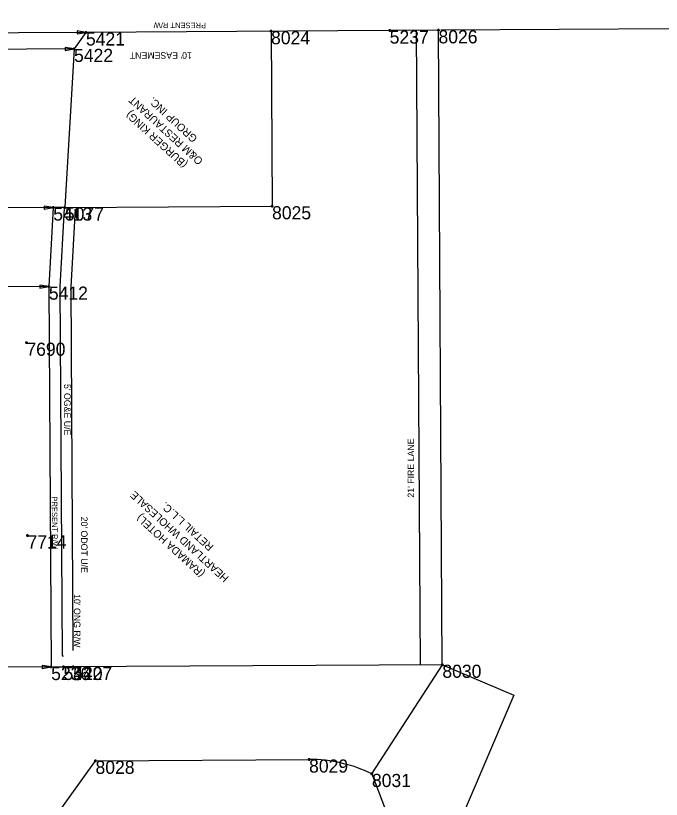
# Model space of a CAD drawing. Extents: x 2145146 to 2158053, y 137507 to 150829.
# Drawn here: x 2150930 to 2151520, y 144848 to 145565 of the extents above; entities that cross this region are included whole.
import ezdxf

# ---------------------------------------------------------------- set-up
doc = ezdxf.new("R2010")
doc.units = 0
for name, color, linetype in [('ALIGN_Cogo Points', 7, 'Continuous'), ('ALIGN_ROW Dimension', 7, 'Continuous'), ('ALIGN_ROW Line', 7, 'Continuous'), ('ALIGN_ROW Text', 7, 'Continuous'), ('PLSS_Easement', 7, 'Continuous'), ('PLSS_Property Line', 7, 'Continuous'), ('PLSS_Text', 7, 'Continuous'), ('PLSS_Text_TURNED OFF', 7, 'Continuous')]:
    doc.layers.add(name, color=color, linetype=linetype)

# ---------------------------------------------------------------- blocks, each defined once
blk = doc.blocks.new('Arrowhd')
at = {"layer": 'PLSS_Property Line'}
blk.add_lwpolyline([(0.125, -0.021), (0.125, 0.021), (0, 0)], close=True, dxfattribs=at)

msp = doc.modelspace()

# ---------------------------------------------------------------- linework, layer by layer
at = {"layer": 'ALIGN_Cogo Points'}
for points in [[(2150994.46, 145549.36), (2150994.46, 145550.56), (2150994.46, 145549.36), (2150993.26, 145549.36), (2150994.46, 145549.36), (2150994.46, 145548.16), (2150994.46, 145549.36), (2150995.66, 145549.36)], [(2151163.64, 145550.46), (2151163.64, 145551.66), (2151163.64, 145550.46), (2151162.44, 145550.46), (2151163.64, 145550.46), (2151163.64, 145549.26), (2151163.64, 145550.46), (2151164.84, 145550.46)], [(2151272.08, 145551.07), (2151272.08, 145552.27), (2151272.08, 145551.07), (2151270.88, 145551.07), (2151272.08, 145551.07), (2151272.08, 145549.87), (2151272.08, 145551.07), (2151273.28, 145551.07)], [(2151316.66, 145551.32), (2151316.66, 145552.52), (2151316.66, 145551.32), (2151315.46, 145551.32), (2151316.66, 145551.32), (2151316.66, 145550.12), (2151316.66, 145551.32), (2151317.86, 145551.32)], [(2150983.58, 145534.3), (2150983.58, 145535.5), (2150983.58, 145534.3), (2150982.38, 145534.3), (2150983.58, 145534.3), (2150983.58, 145533.1), (2150983.58, 145534.3), (2150984.78, 145534.3)], [(2150964.56, 145389.31), (2150964.56, 145390.51), (2150964.56, 145389.31), (2150963.36, 145389.31), (2150964.56, 145389.31), (2150964.56, 145388.11), (2150964.56, 145389.31), (2150965.76, 145389.31)], [(2150975.26, 145389.37), (2150975.26, 145390.57), (2150975.26, 145389.37), (2150974.06, 145389.37), (2150975.26, 145389.37), (2150975.26, 145388.17), (2150975.26, 145389.37), (2150976.46, 145389.37)], [(2151164.56, 145390.47), (2151164.56, 145391.67), (2151164.56, 145390.47), (2151163.36, 145390.47), (2151164.56, 145390.47), (2151164.56, 145389.27), (2151164.56, 145390.47), (2151165.76, 145390.47)], [(2150960.58, 145317), (2150960.58, 145318.2), (2150960.58, 145317), (2150959.38, 145317), (2150960.58, 145317), (2150960.58, 145315.8), (2150960.58, 145317), (2150961.78, 145317)], [(2150940.05, 145265.73), (2150940.05, 145266.93), (2150940.05, 145265.73), (2150938.85, 145265.73), (2150940.05, 145265.73), (2150940.05, 145264.53), (2150940.05, 145265.73), (2150941.25, 145265.73)], [(2150941.1, 145089.57), (2150941.1, 145090.77), (2150941.1, 145089.57), (2150939.9, 145089.57), (2150941.1, 145089.57), (2150941.1, 145088.37), (2150941.1, 145089.57), (2150942.3, 145089.57)], [(2151320.21, 144971.36), (2151320.21, 144972.56), (2151320.21, 144971.36), (2151319.01, 144971.36), (2151320.21, 144971.36), (2151320.21, 144970.16), (2151320.21, 144971.36), (2151321.41, 144971.36)], [(2150962.67, 144969.29), (2150962.67, 144970.49), (2150962.67, 144969.29), (2150961.47, 144969.29), (2150962.67, 144969.29), (2150962.67, 144968.09), (2150962.67, 144969.29), (2150963.87, 144969.29)], [(2150973.99, 144969.36), (2150973.99, 144970.56), (2150973.99, 144969.36), (2150972.79, 144969.36), (2150973.99, 144969.36), (2150973.99, 144968.16), (2150973.99, 144969.36), (2150975.19, 144969.36)], [(2150982.69, 144969.28), (2150982.69, 144970.48), (2150982.69, 144969.28), (2150981.49, 144969.28), (2150982.69, 144969.28), (2150982.69, 144968.08), (2150982.69, 144969.28), (2150983.89, 144969.28)], [(2151003.22, 144883.54), (2151003.22, 144884.74), (2151003.22, 144883.54), (2151002.02, 144883.54), (2151003.22, 144883.54), (2151003.22, 144882.34), (2151003.22, 144883.54), (2151004.42, 144883.54)], [(2151198.4, 144884.72), (2151198.4, 144885.92), (2151198.4, 144884.72), (2151197.2, 144884.72), (2151198.4, 144884.72), (2151198.4, 144883.52), (2151198.4, 144884.72), (2151199.6, 144884.72)], [(2151255.84, 144871.52), (2151255.84, 144872.72), (2151255.84, 144871.52), (2151254.64, 144871.52), (2151255.84, 144871.52), (2151255.84, 144870.32), (2151255.84, 144871.52), (2151257.04, 144871.52)]]:
    msp.add_lwpolyline(points, dxfattribs=at)
at = {"layer": 'ALIGN_ROW Dimension'}
for points in [[(2150994.46, 145549.36), (2150809.35, 145548.25)], [(2150983.58, 145534.3), (2150809.44, 145533.25)], [(2150964.56, 145389.31), (2150810.31, 145388.39)], [(2150960.58, 145317), (2150810.74, 145316.1)], [(2150962.66, 144969.3), (2150812.83, 144968.4)]]:
    msp.add_lwpolyline(points, dxfattribs=at)
at = {"layer": 'ALIGN_ROW Line'}
for points in [[(2151901.3, 145564.63), (2151901.3, 145564.63), (2151751.23, 145563.78), (2151751.29, 145553.78), (2151318.93, 145551.33)], [(2151316.66, 145551.32), (2150994.46, 145549.36), (2150983.58, 145534.3), (2150975.27, 145389.44)], [(2150964.56, 145389.31), (2150960.58, 145317), (2150962.67, 144969.29), (2150973.99, 144969.36)], [(2150975.26, 145389.37), (2150964.56, 145389.31)]]:
    msp.add_lwpolyline(points, dxfattribs=at)
at = {"layer": 'PLSS_Easement'}
for points in [[(2151300.13, 144971.21), (2151296.65, 145551.17)], [(2150974.55, 145388.76), (2150970.58, 145316.75), (2150972.6, 144979.35), (2150973.93, 144979.36)], [(2150984.53, 145388.21), (2150980.58, 145316.51), (2150982.57, 144984.38)]]:
    msp.add_lwpolyline(points, dxfattribs=at)
at = {"layer": 'PLSS_Property Line'}
for p, q in [((2151255.84, 144871.52), (2151320.21, 144971.36)), ((2151320.21, 144971.36), (2151385.43, 144943.51)), ((2151385.43, 144943.51), (2151327.59, 144807.73))]:
    msp.add_line(p, q, dxfattribs=at)
for points in [[(2151163.62, 145550.39), (2151164.56, 145390.47)], [(2151163.64, 145550.46), (2151164.56, 145390.47)], [(2151320.13, 144971.33), (2151316.65, 145551.29)], [(2150975.26, 145389.37), (2151164.56, 145390.47)], [(2151320.13, 144971.36), (2150973.99, 144969.36)], [(2150966.92, 144832.96), (2151003.22, 144883.54), (2151198.4, 144884.72), (2151198.4, 144884.72)], [(2151255.84, 144871.52), (2151255.84, 144871.52), (2151270.67, 144832.3)]]:
    msp.add_lwpolyline(points, dxfattribs=at)
msp.add_arc((2151199.18, 144756.57), 128.15, 63.7592, 90.34776, dxfattribs=at)

# ---------------------------------------------------------------- block references
at = {"layer": 'ALIGN_ROW Dimension', "xscale": 65.00000000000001, "yscale": 64.99999999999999, "rotation": -179.65177652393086}
for p in [(2150994.46, 145549.36), (2150983.58, 145534.3), (2150964.56, 145389.31), (2150960.58, 145317), (2150962.66, 144969.3)]:
    msp.add_blockref('Arrowhd', p, dxfattribs=at)

# ---------------------------------------------------------------- texts
at = {"layer": 'ALIGN_Cogo Points'}
for s, p in [('5421', (2150994.46, 145537.36)), ('8024', (2151163.64, 145538.46)), ('5237', (2151272.08, 145539.07)), ('8026', (2151316.66, 145539.32)), ('5422', (2150983.58, 145522.3)), ('5413', (2150964.56, 145377.31)), ('5077', (2150975.26, 145377.37)), ('8025', (2151164.56, 145378.47)), ('5412', (2150960.58, 145305)), ('7690', (2150940.05, 145253.73)), ('7714', (2150941.1, 145077.57)), ('5236', (2150962.67, 144957.29)), ('5420', (2150973.99, 144957.36)), ('5427', (2150982.69, 144957.28)), ('8030', (2151320.21, 144959.36)), ('8028', (2151003.22, 144871.54)), ('8029', (2151198.4, 144872.72)), ('8031', (2151255.84, 144859.52))]:
    msp.add_text(s, height=12, dxfattribs=at).set_placement(p)
at = {"layer": 'ALIGN_ROW Text'}
for rotation, p in [(179.73131, (2151104.31, 145558.18)), (270.6018, (2150963.19, 145125.17))]:
    msp.add_text('PRESENT R/W', height=5, rotation=rotation, dxfattribs=at).set_placement(p)
at = {"layer": 'PLSS_Text'}
for s, rotation, p in [("10' EASEMENT", 180, (2151091.29, 145531.24)), ("5' OG&E U/E", 270, (2150974.51, 145227.96)), ("21' FIRE LANE", 90, (2151294.43, 145124.03)), ("20' ODOT U/E", 270, (2150989.94, 145106.71)), ("10' ONG R/W", 270, (2150983.45, 145035.86))]:
    msp.add_text(s, height=6, rotation=rotation, dxfattribs=at).set_placement(p)
at = {"layer": 'PLSS_Text_TURNED OFF'}
for s, p in [('O&M RESTAURANT', (2151101.98, 145432.62)), ('GROUP INC.', (2151096.88, 145453.15)), ('(BURGER KING)', (2151087.84, 145429.72)), ('HEARTLAND WHOLESALE', (2151125.54, 145051.27)), ('RETAIL L.L.C.', (2151111.65, 145079.85)), ('(RAMADA HOTEL)', (2151103.59, 145055.53))]:
    msp.add_text(s, height=7, rotation=137.49751, dxfattribs=at).set_placement(p)

doc.saveas('drawing.dxf')
